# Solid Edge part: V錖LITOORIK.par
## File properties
Author: Türk
Template: Iso Part.par
Last saved by: Türk
Revision: 22
Application: Solid Edge
Accuracy: 0,990
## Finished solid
Body 1: solid body, 43 faces, 98 edges, 56 vertices.
  Faces by surface: plane 28, cylinder 15
  Edges by curve: line 68, circle 30
Bounding box of the edges (mm): 64.000 x 756.220 x 64.000, from (-32, -536.22, -32) to (32, 220, 32).
Cylindrical faces by radius (mm): R7.5 x4, R10 x8, R27.5 x1, R32 x2
Planar faces by outward normal: +x 4, +y 4, +z 4, -x 4, -y 4, -z 4, oblique 4
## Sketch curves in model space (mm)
line (-27.5, 170, -27.5) -> (-27.5, 170, 27.5)
line (-27.5, 170, 27.5) -> (27.5, 170, 27.5)
line (27.5, 170, 27.5) -> (27.5, 170, -27.5)
line (27.5, 170, -27.5) -> (-27.5, 170, -27.5)
line (-27.5, 220, 0) -> (-27.5, 205, 0)
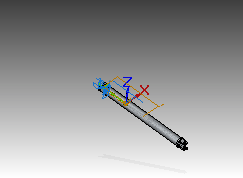
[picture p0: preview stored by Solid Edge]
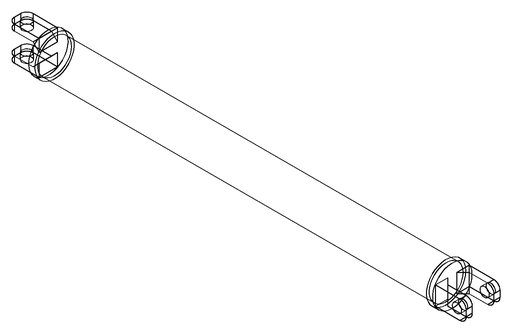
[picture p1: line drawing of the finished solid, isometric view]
